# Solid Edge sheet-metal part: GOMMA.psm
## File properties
Author: f_grande
Template: Normal.psm
Last saved by: f_grande
Revision: 3
Application: Solid Edge
Material: Plexiglas
Stile della faccia: Bianco (vetro)
Stile di riempimento: ANSI34(Plastica)
Stile virtuale: Marroncino (lucido)
Coef. of Thermal Exp: 0.0
Thermal Conductivity: 1.5
Specific Heat: 0.0
Modulus of Elasticity: 2757902.8
Poisson's Ratio: 0.4
Yield Stress: 6894757.0
Ultimate Stress: 0.0
Elongation: 0.0
Tipo di contenuto documento: 0
Density: 1385,000 kg/m^3
Accuracy: 0,990
Material Thickness: 40,00 mm
Bend Radius: 1,00 mm
Relief Width: 1,00 mm
Relief Length: 0,00 mm
Neutral Factor: 0,330
Minimum Arc Length: 0,10 mm
Deviational Tolerance: 0,10 mm
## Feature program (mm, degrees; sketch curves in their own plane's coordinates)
base tab "unnamed BaseTab 1"
sketch for "unnamed Cutout 1" plane through (28.1983, -97.5262, -20) normal (0, -1, 0) x-axis (1, 0, 0)
  line (-55.5, -20) -> (-55.5, 0)
  line (-55.5, 0) -> (-54.5, 0)
  line (-54.5, 0) -> (-54.5, -20)
  line (-54.5, -20) -> (-55.5, -20)
  dimension (linear) = 54.5
  dimension (linear) = 54.5
extrude "unnamed Cutout 1" cut
pattern "unnamed Pattern 1" of "unnamed Cutout 1"
pattern "unnamed Pattern 2"
sketch for "ExtrudedCutout_2" plane through (114.6983, -34.0262, -20) normal (1, 0, 0) x-axis (0, 1, 0)
  line (-53.5, -20) -> (-53.5, 0)
  line (-53.5, 0) -> (-52.5, 0)
  line (-52.5, 0) -> (-52.5, -20)
  line (-52.5, -20) -> (-53.5, -20)
  dimension (linear) = 52.5
extrude "ExtrudedCutout_2" cut
sketch for "ExtrudedCutout_3" #1 plane through (114.6983, -34.0262, -20) normal (1, 0, 0) x-axis (0, 1, 0)
  line (-22.5, -20) -> (-22.5, 0)
  line (-22.5, 0) -> (-23.5, 0)
  line (-23.5, 0) -> (-23.5, -20)
  line (-23.5, -20) -> (-22.5, -20)
sketch for "ExtrudedCutout_3" #2 plane through (114.6983, -34.0262, -20) normal (1, 0, 0) x-axis (0, 1, 0)
  line (-8.5, -20) -> (-8.5, 0)
  line (-8.5, 0) -> (-7.5, 0)
  line (-7.5, 0) -> (-7.5, -20)
  line (-7.5, -20) -> (-8.5, -20)
sketch for "ExtrudedCutout_3" #3 plane through (114.6983, -34.0262, -20) normal (1, 0, 0) x-axis (0, 1, 0)
  line (6.5, -20) -> (6.5, 0)
  line (6.5, 0) -> (7.5, 0)
  line (7.5, 0) -> (7.5, -20)
  line (7.5, -20) -> (6.5, -20)
sketch for "ExtrudedCutout_3" #4 plane through (114.6983, -34.0262, -20) normal (1, 0, 0) x-axis (0, 1, 0)
  line (21.5, -20) -> (21.5, 0)
  line (21.5, 0) -> (22.5, 0)
  line (22.5, 0) -> (22.5, -20)
  line (22.5, -20) -> (21.5, -20)
sketch for "ExtrudedCutout_3" #5 plane through (114.6983, -34.0262, -20) normal (1, 0, 0) x-axis (0, 1, 0)
  line (36.5, -20.2795) -> (36.5, -0.2795)
  line (36.5, -0.2795) -> (37.5, -0.2795)
  line (37.5, -0.2795) -> (37.5, -20.2795)
  line (37.5, -20.2795) -> (36.5, -20.2795)
sketch for "ExtrudedCutout_3" #6 plane through (114.6983, -34.0262, -20) normal (1, 0, 0) x-axis (0, 1, 0)
  line (51.5, 0) -> (51.5, -20)
  line (51.5, -20) -> (52.5, -20)
  line (52.5, -20) -> (52.5, 0)
  line (52.5, 0) -> (51.5, 0)
sketch for "ExtrudedCutout_3" #7 plane through (114.6983, -34.0262, -20) normal (1, 0, 0) x-axis (0, 1, 0)
  line (-38.5, -20) -> (-38.5, 0)
  line (-38.5, 0) -> (-37.5, 0)
  line (-37.5, 0) -> (-37.5, -20)
  line (-37.5, -20) -> (-38.5, -20)
  dimension (linear) = 37.5
  dimension (linear) = 37.5
  dimension (linear) = 37.5
extrude "ExtrudedCutout_3" cut
sketch for "Foro_1" plane through (28.1983, -97.5262, -20) normal (0, -1, 0) x-axis (1, 0, 0)
  hole centre (-53.3188, 12.1453) bore radius 1
hole "Foro_1"
sketch for "unnamed Hole 1" plane through (28.1983, -97.5262, -20) normal (0, -1, 0) x-axis (1, 0, 0)
  hole centre (-1.6366, 12.1453) bore radius 1
hole "unnamed Hole 1"
sketch for "unnamed Hole 2" plane through (28.1983, -97.5262, -20) normal (0, -1, 0) x-axis (1, 0, 0)
  hole centre (57.6256, 12.1453) bore radius 1
hole "unnamed Hole 2"
sketch for "Foro_4" plane through (114.6983, -34.0262, -20) normal (1, 0, 0) x-axis (0, 1, 0)
  hole centre (-22.5, 14.2521) bore radius 1
hole "Foro_4"
sketch for "unnamed Hole 3" plane through (114.6983, -34.0262, -20) normal (1, 0, 0) x-axis (0, 1, 0)
  hole centre (29.8722, 14.2521) bore radius 1
hole "unnamed Hole 3"
pattern "unnamed Pattern 3" of "Foro_1", "unnamed Hole 1", "unnamed Hole 2"
pattern "unnamed Pattern 4" of "Foro_4", "unnamed Hole 3"
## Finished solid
Body 1: solid body, 134 faces, 388 edges, 248 vertices.
  Faces by surface: plane 122, cylinder 12
  Edges by curve: line 356, circle 32
Bounding box of the edges (mm): 152.000 x 127.000 x 40.000, from (-37.3017, -97.5262, -40) to (114.6983, 29.4738, 0).
Cylindrical faces by radius (mm): R1 x8, R20 x2, R21 x2
Planar faces by outward normal: +x 21, +y 10, +z 1, -x 23, -y 10, -z 57
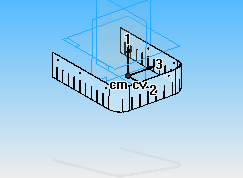
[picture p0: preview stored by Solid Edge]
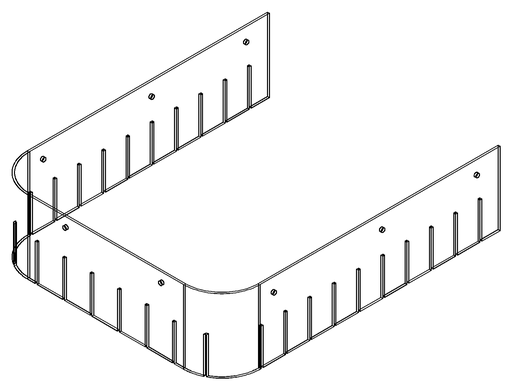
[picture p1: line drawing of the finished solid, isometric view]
